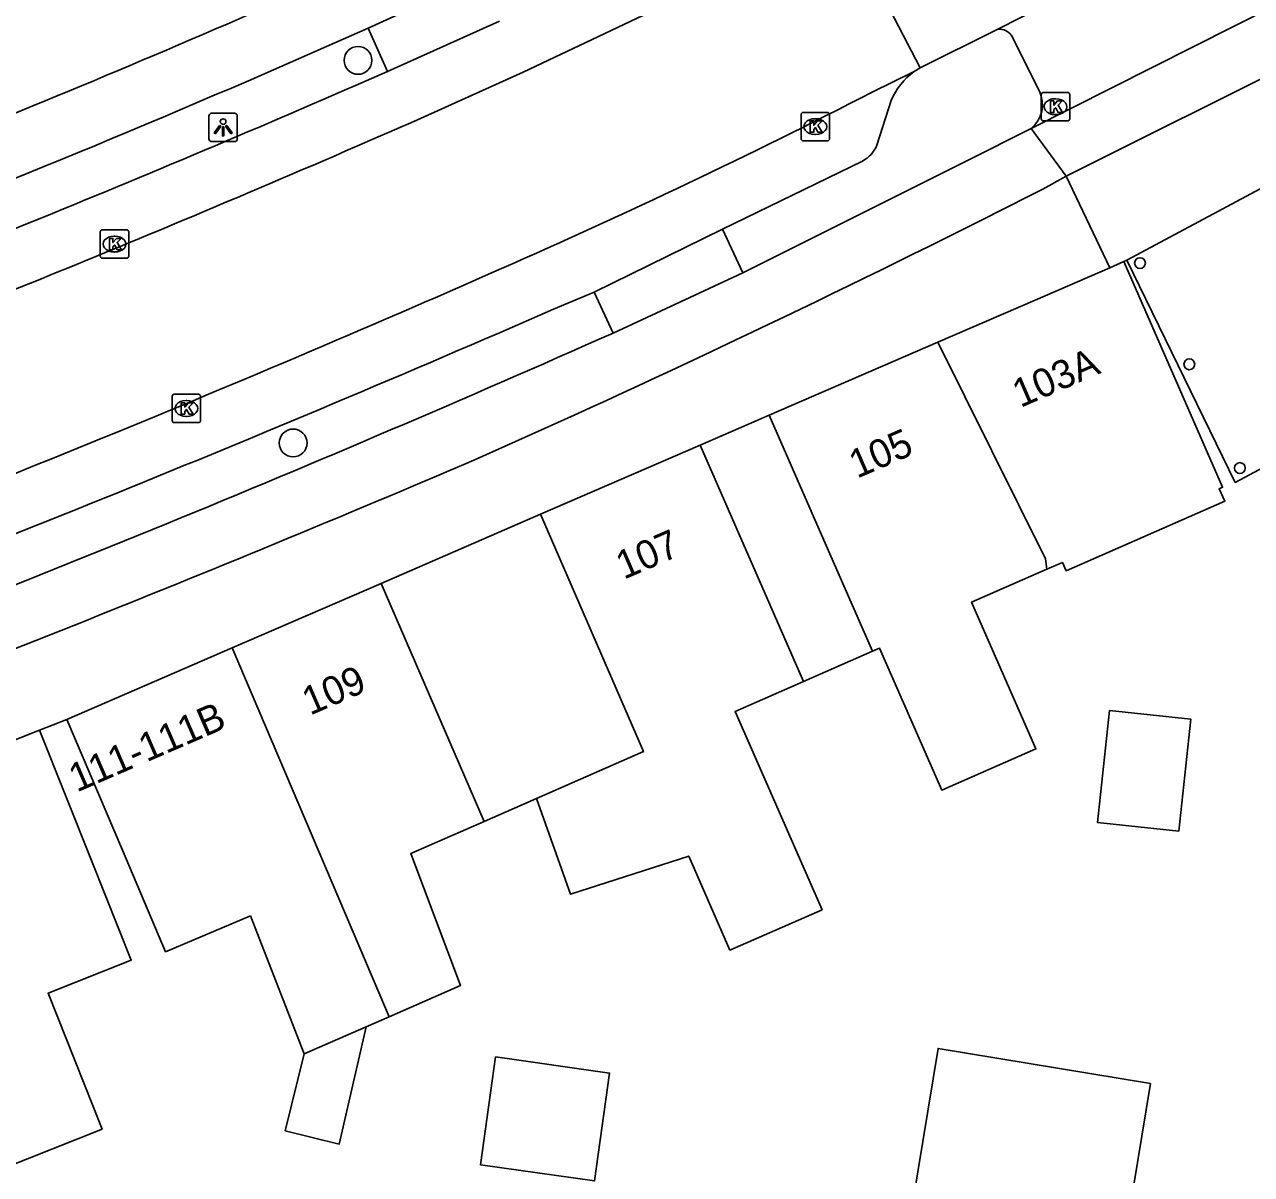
# Model space of a CAD drawing. Extents: x 158087 to 159494, y 382905 to 383981.
# Drawn here: x 158823.32 to 158866.48, y 383142.93 to 383183.38 of the extents above; entities that cross this region are included whole.
import ezdxf

# ---------------------------------------------------------------- set-up
doc = ezdxf.new("R2010")
doc.units = 0
for name, color, linetype in [('IMGEO_Boom', 7, 'Continuous'), ('IMGEO_Fietspad_gesloten', 7, 'Continuous'), ('IMGEO_Kolk', 7, 'Continuous'), ('IMGEO_Lichtpunt', 7, 'Continuous'), ('IMGEO_Pand', 7, 'Continuous'), ('IMGEO_Pand_nummerreeks', 7, 'Continuous'), ('IMGEO_Pand_overbouw', 7, 'Continuous'), ('IMGEO_Parkeervlak_open', 7, 'Continuous'), ('IMGEO_Rijbaan_lokaal_gesloten', 7, 'Continuous'), ('IMGEO_Rijbaan_lokaal_open', 7, 'Continuous'), ('IMGEO_Voetpad_open', 7, 'Continuous')]:
    doc.layers.add(name, color=color, linetype=linetype)

msp = doc.modelspace()

# ---------------------------------------------------------------- linework, layer by layer
at = {"layer": 'IMGEO_Boom'}
for centre in [(158835.051, 383182.122), (158832.77, 383168.665)]:
    msp.add_circle(centre, 0.489, dxfattribs=at)
at = {"layer": 'IMGEO_Fietspad_gesloten'}
for points in [[(158835.404, 383183.261), (158839.326, 383185.052)], [(158835.404, 383183.261), (158831.196, 383181.409)], [(158859.959, 383178.045), (158868.202, 383182.167)], [(158858.726, 383179.723), (158856.446, 383178.582), (158848.592, 383174.652)], [(158859.959, 383178.045), (158858.726, 383179.723)], [(158857.375, 383176.704), (158859.134, 383177.597), (158859.959, 383178.045)], [(158848.592, 383174.652), (158844.027, 383172.532)]]:
    msp.add_lwpolyline(points, dxfattribs=at)
for centre, radius, start, end in [((158667.794, 383559.163), 409.453, 290.48758, 294.63801), ((158680.752, 383529.5), 379.211, 290.2208, 293.37386), ((158673.769, 383540.669), 407.654, 293.94378, 296.76918), ((158605.706, 383708.872), 586.905, 290.623264, 293.957785), ((158601.103, 383724.492), 605.204, 290.267786, 293.168326)]:
    msp.add_arc(centre, radius, start, end, dxfattribs=at)
at = {"layer": 'IMGEO_Kolk'}
for p, q in [((158859.085, 383180.068), (158859.085, 383180.92)), ((158859.16, 383180.994), (158860.012, 383180.994)), ((158859.573, 383180.774), (158859.598, 383180.774)), ((158860.086, 383180.92), (158860.086, 383180.068)), ((158850.713, 383180.292), (158851.565, 383180.292)), ((158850.638, 383179.366), (158850.638, 383180.218)), ((158851.126, 383180.072), (158851.151, 383180.072)), ((158851.639, 383180.218), (158851.639, 383179.366)), ((158860.012, 383179.994), (158859.16, 383179.994)), ((158859.596, 383180.214), (158859.571, 383180.214)), ((158851.149, 383179.512), (158851.124, 383179.512)), ((158851.565, 383179.292), (158850.713, 383179.292)), ((158825.985, 383175.236), (158825.985, 383176.088)), ((158826.06, 383176.162), (158826.912, 383176.162)), ((158826.473, 383175.942), (158826.498, 383175.942)), ((158826.986, 383176.088), (158826.986, 383175.236)), ((158826.912, 383175.162), (158826.06, 383175.162)), ((158826.496, 383175.382), (158826.471, 383175.382)), ((158828.514, 383169.453), (158828.514, 383170.305)), ((158828.589, 383170.379), (158829.441, 383170.379)), ((158829.515, 383170.305), (158829.515, 383169.453)), ((158829.002, 383170.159), (158829.027, 383170.159)), ((158829.025, 383169.599), (158829, 383169.599)), ((158829.441, 383169.379), (158828.589, 383169.379))]:
    msp.add_line(p, q, dxfattribs=at)
for points in [[(158859.085, 383180.068), (158859.085, 383180.92)], [(158859.16, 383180.994), (158860.012, 383180.994)], [(158859.406, 383180.694), (158859.529, 383180.694), (158859.529, 383180.543), (158859.659, 383180.694), (158859.823, 383180.694), (158859.677, 383180.543), (158859.83, 383180.294), (158859.678, 383180.294), (158859.593, 383180.458), (158859.529, 383180.391), (158859.529, 383180.294), (158859.406, 383180.294), (158859.406, 383180.694)], [(158860.086, 383180.92), (158860.086, 383180.068)], [(158850.713, 383180.292), (158851.565, 383180.292)], [(158850.638, 383179.366), (158850.638, 383180.218)], [(158850.959, 383179.992), (158851.082, 383179.992), (158851.082, 383179.841), (158851.212, 383179.992), (158851.376, 383179.992), (158851.23, 383179.841), (158851.383, 383179.592), (158851.231, 383179.592), (158851.146, 383179.756), (158851.082, 383179.689), (158851.082, 383179.592), (158850.959, 383179.592), (158850.959, 383179.992)], [(158851.639, 383180.218), (158851.639, 383179.366)], [(158860.012, 383179.994), (158859.16, 383179.994)], [(158851.565, 383179.292), (158850.713, 383179.292)], [(158825.985, 383175.236), (158825.985, 383176.088)], [(158826.06, 383176.162), (158826.912, 383176.162)], [(158826.986, 383176.088), (158826.986, 383175.236)], [(158826.306, 383175.862), (158826.429, 383175.862), (158826.429, 383175.711), (158826.559, 383175.862), (158826.723, 383175.862), (158826.577, 383175.711), (158826.73, 383175.462), (158826.578, 383175.462), (158826.493, 383175.626), (158826.429, 383175.559), (158826.429, 383175.462), (158826.306, 383175.462), (158826.306, 383175.862)], [(158826.912, 383175.162), (158826.06, 383175.162)], [(158828.514, 383169.453), (158828.514, 383170.305)], [(158828.589, 383170.379), (158829.441, 383170.379)], [(158829.515, 383170.305), (158829.515, 383169.453)], [(158828.835, 383170.079), (158828.958, 383170.079), (158828.958, 383169.928), (158829.088, 383170.079), (158829.252, 383170.079), (158829.106, 383169.928), (158829.259, 383169.679), (158829.107, 383169.679), (158829.022, 383169.843), (158828.958, 383169.776), (158828.958, 383169.679), (158828.835, 383169.679), (158828.835, 383170.079)], [(158829.441, 383169.379), (158828.589, 383169.379)]]:
    msp.add_lwpolyline(points, dxfattribs=at)
for centre, start, end in [((158859.162, 383180.918), 91.552, 178.448), ((158859.162, 383180.918), 91.552, 178.448), ((158860.01, 383180.918), 1.552, 88.448), ((158860.01, 383180.918), 1.552, 88.448), ((158850.715, 383180.216), 91.552, 178.448), ((158850.715, 383180.216), 91.552, 178.448), ((158851.563, 383180.216), 1.552, 88.448), ((158851.563, 383180.216), 1.552, 88.448), ((158859.162, 383180.07), 181.552, 268.448), ((158859.162, 383180.07), 181.552, 268.448), ((158860.01, 383180.07), 271.552, 358.448), ((158860.01, 383180.07), 271.552, 358.448), ((158850.715, 383179.368), 181.552, 268.448), ((158850.715, 383179.368), 181.552, 268.448), ((158851.563, 383179.368), 271.552, 358.448), ((158851.563, 383179.368), 271.552, 358.448), ((158826.062, 383176.086), 91.552, 178.448), ((158826.062, 383176.086), 91.552, 178.448), ((158826.91, 383176.086), 1.552, 88.448), ((158826.91, 383176.086), 1.552, 88.448), ((158826.062, 383175.238), 181.552, 268.448), ((158826.062, 383175.238), 181.552, 268.448), ((158826.91, 383175.238), 271.552, 358.448), ((158826.91, 383175.238), 271.552, 358.448), ((158828.591, 383170.303), 91.552, 178.448), ((158828.591, 383170.303), 91.552, 178.448), ((158829.439, 383170.303), 1.552, 88.448), ((158829.439, 383170.303), 1.552, 88.448), ((158828.591, 383169.455), 181.552, 268.448), ((158828.591, 383169.455), 181.552, 268.448), ((158829.439, 383169.455), 271.552, 358.448), ((158829.439, 383169.455), 271.552, 358.448)]:
    msp.add_arc(centre, 0.0765, start, end, dxfattribs=at)
for centre, major_axis, ratio, start_param, end_param in [((158859.572, 383180.494), (-0.387, 0.002), 0.722429, 4.712389, 7.853982), ((158859.597, 383180.494), (-0.39, 0.002), 0.717154, 1.570796, 4.712389), ((158851.125, 383179.792), (-0.387, 0.002), 0.722429, 4.712389, 7.853982), ((158851.15, 383179.792), (-0.39, 0.002), 0.717154, 1.570796, 4.712389), ((158826.472, 383175.662), (-0.387, 0.002), 0.722429, 4.712389, 7.853982), ((158826.497, 383175.662), (-0.39, 0.002), 0.717154, 1.570796, 4.712389), ((158829.001, 383169.879), (-0.387, 0.002), 0.722429, 4.712389, 7.853982), ((158829.026, 383169.879), (-0.39, 0.002), 0.717154, 1.570796, 4.712389)]:
    msp.add_ellipse(centre, major_axis=major_axis, ratio=ratio, start_param=start_param, end_param=end_param, dxfattribs=at)
at = {"layer": 'IMGEO_Lichtpunt'}
for p, q in [((158830.711, 383180.264), (158829.903, 383180.264)), ((158830.711, 383180.264), (158829.903, 383180.264)), ((158829.809, 383180.169), (158829.809, 383179.362)), ((158829.809, 383180.169), (158829.809, 383179.362)), ((158830.805, 383179.362), (158830.805, 383180.169)), ((158830.805, 383179.362), (158830.805, 383180.169)), ((158829.903, 383179.268), (158830.711, 383179.268)), ((158829.903, 383179.268), (158830.711, 383179.268))]:
    msp.add_line(p, q, dxfattribs=at)
for points in [[(158830.183, 383179.833), (158830.222, 383179.805), (158830.034, 383179.543), (158829.996, 383179.57), (158830.183, 383179.833)], [(158830.395, 383179.805), (158830.433, 383179.832), (158830.62, 383179.57), (158830.581, 383179.542), (158830.395, 383179.805)], [(158830.285, 383179.785), (158830.332, 383179.785), (158830.332, 383179.463), (158830.285, 383179.463), (158830.285, 383179.785)]]:
    msp.add_lwpolyline(points, dxfattribs=at)
msp.add_circle((158830.308, 383179.967), 0.0994, dxfattribs=at)
for centre, start, end in [((158829.903, 383180.169), 90, 180), ((158829.903, 383180.169), 90, 180), ((158830.711, 383180.169), 0, 90), ((158830.711, 383180.169), 0, 90), ((158829.903, 383179.362), 180, 270), ((158829.903, 383179.362), 180, 270), ((158830.711, 383179.362), 270, 0), ((158830.711, 383179.362), 270, 360)]:
    msp.add_arc(centre, 0.0946, start, end, dxfattribs=at)
at = {"layer": 'IMGEO_Pand'}
for points in [[(158855.445, 383172.209), (158858.865, 383173.69), (158861.498, 383174.83)], [(158861.987, 383175.042), (158863.993, 383170.463), (158865.464, 383167.106), (158865.342, 383167.053), (158865.536, 383166.613), (158859.956, 383164.168), (158859.827, 383164.462), (158859.275, 383164.22)], [(158861.987, 383175.042), (158861.498, 383174.83)], [(158849.517, 383169.641), (158855.445, 383172.209)], [(158859.275, 383164.22), (158859.237, 383164.591), (158855.445, 383172.209)], [(158859.275, 383164.22), (158856.636, 383163.064), (158858.897, 383157.902), (158855.583, 383156.451), (158853.395, 383161.445), (158853.154, 383161.339), (158851.523, 383165.062), (158849.517, 383169.641)], [(158847.086, 383168.587), (158850.727, 383160.276), (158848.317, 383159.22), (158851.374, 383152.242), (158848.134, 383150.823), (158846.685, 383154.13), (158842.523, 383152.792), (158841.331, 383156.16)], [(158841.474, 383166.156), (158847.086, 383168.587)], [(158835.861, 383163.725), (158841.474, 383166.156)], [(158841.474, 383166.156), (158845.091, 383157.807), (158841.331, 383156.16)], [(158830.622, 383161.455), (158835.861, 383163.725)], [(158839.488, 383155.353), (158835.861, 383163.725)], [(158824.804, 383158.935), (158830.622, 383161.455)], [(158830.622, 383161.455), (158836.016, 383148.784), (158836.144, 383148.482)], [(158861.481, 383159.254), (158864.34, 383158.949), (158863.921, 383155.013), (158861.062, 383155.317), (158861.481, 383159.254)], [(158833.154, 383147.172), (158831.27, 383152.029), (158828.285, 383150.768), (158826.768, 383154.338), (158824.804, 383158.935)], [(158817.959, 383156.215), (158823.85, 383158.562)], [(158823.85, 383158.562), (158825.7, 383153.918), (158827.074, 383150.47), (158824.149, 383149.305), (158826.052, 383144.527), (158822.57, 383143.14)], [(158841.331, 383156.16), (158839.488, 383155.353)], [(158839.488, 383155.353), (158836.913, 383154.225), (158838.659, 383149.584), (158836.144, 383148.482)], [(158836.144, 383148.482), (158835.336, 383148.128)], [(158835.336, 383148.128), (158834.389, 383144.002), (158832.486, 383144.473), (158833.154, 383147.172)], [(158835.336, 383148.128), (158833.154, 383147.172)], [(158839.89, 383147.065), (158843.903, 383146.501), (158843.37, 383142.708), (158839.357, 383143.272), (158839.89, 383147.065)], [(158854.375, 383140.825), (158855.457, 383147.364), (158862.926, 383146.128), (158861.866, 383139.722), (158857.466, 383140.45)]]:
    msp.add_lwpolyline(points, dxfattribs=at)
for centre, start, end in [((158862.557, 383174.992), 0, 180), ((158862.557, 383174.992), 180, 0), ((158864.292, 383171.432), 360, 180), ((158864.292, 383171.432), 180, 360), ((158866.07, 383167.782), 360, 180), ((158866.07, 383167.782), 180, 360)]:
    msp.add_arc(centre, 0.19, start, end, dxfattribs=at)
at = {"layer": 'IMGEO_Pand_overbouw'}
for points in [[(158868.978, 383178.782), (158862.093, 383175.099), (158865.906, 383167.274), (158872.934, 383171.032)], [(158851.523, 383165.062), (158849.517, 383169.641), (158847.086, 383168.587), (158850.727, 383160.276), (158853.154, 383161.339)]]:
    msp.add_lwpolyline(points, close=True, dxfattribs=at)
at = {"layer": 'IMGEO_Parkeervlak_open'}
for points in [[(158853.806, 383180.716), (158853.301, 383179.136)], [(158852.801, 383178.582), (158847.872, 383176.182)], [(158843.354, 383173.967), (158841.925, 383173.366)]]:
    msp.add_lwpolyline(points, dxfattribs=at)
for centre, radius, start, end in [((158636.98, 383635.164), 495.221, 290.65054, 293.70774), ((158856.079, 383179.744), 2.472, 126.4268, 156.8469), ((158852.263, 383179.57), 1.125, 298.5567, 337.309), ((158589.725, 383751.197), 630.471, 290.539505, 293.579302)]:
    msp.add_arc(centre, radius, start, end, dxfattribs=at)
at = {"layer": 'IMGEO_Rijbaan_lokaal_gesloten'}
for points in [[(158836.906, 383179.93), (158840.865, 383181.709), (158852.132, 383187.055)], [(158854.611, 383181.733), (158853.131, 383181.002)], [(158854.827, 383181.857), (158854.611, 383181.733)]]:
    msp.add_lwpolyline(points, dxfattribs=at)
for centre, radius, start, end in [((158744.682, 383392.065), 237.295, 293.70899, 297.19518), ((158636.278, 383636.867), 499.042, 290.65709, 293.70493), ((158619.364, 383674.961), 546.705, 290.51582, 293.81287)]:
    msp.add_arc(centre, radius, start, end, dxfattribs=at)
at = {"layer": 'IMGEO_Rijbaan_lokaal_open'}
for points in [[(158867.85, 383188.448), (158857.535, 383183.208)], [(158852.132, 383187.055), (158854.827, 383181.857)], [(158867.264, 383184.027), (158858.726, 383179.723)], [(158857.535, 383183.208), (158854.827, 383181.857)], [(158858.078, 383182.929), (158859.017, 383181.036)]]:
    msp.add_lwpolyline(points, dxfattribs=at)
for centre, radius, start, end in [((158857.625, 383182.714), 0.502, 25.3352, 100.2755), ((158858.057, 383180.56), 1.072, 308.6491, 26.358)]:
    msp.add_arc(centre, radius, start, end, dxfattribs=at)
at = {"layer": 'IMGEO_Voetpad_open'}
for points in [[(158836.094, 383181.736), (158835.404, 383183.261)], [(158840.034, 383183.506), (158836.094, 383181.736)], [(158868.978, 383178.782), (158862.093, 383175.099), (158861.987, 383175.042)], [(158861.498, 383174.83), (158859.959, 383178.045)], [(158843.354, 383173.967), (158847.872, 383176.182)], [(158847.872, 383176.182), (158848.592, 383174.652)], [(158844.027, 383172.532), (158843.354, 383173.967)], [(158849.517, 383169.641), (158847.086, 383168.587)], [(158824.804, 383158.935), (158823.85, 383158.562)]]:
    msp.add_lwpolyline(points, dxfattribs=at)

# ---------------------------------------------------------------- texts
at = {"layer": 'IMGEO_Pand_nummerreeks'}
for s, rotation, p in [('103A', 23.4149, (158858.351, 383169.893)), ('105', 23.4222, (158852.603, 383167.403)), ('107', 23.4225, (158844.402, 383163.849)), ('109', 23.4282, (158833.364, 383159.068)), ('111-111B', 23.4168, (158825.158, 383156.364))]:
    msp.add_text(s, height=1, rotation=rotation, dxfattribs=at).set_placement(p)

doc.saveas('drawing.dxf')
